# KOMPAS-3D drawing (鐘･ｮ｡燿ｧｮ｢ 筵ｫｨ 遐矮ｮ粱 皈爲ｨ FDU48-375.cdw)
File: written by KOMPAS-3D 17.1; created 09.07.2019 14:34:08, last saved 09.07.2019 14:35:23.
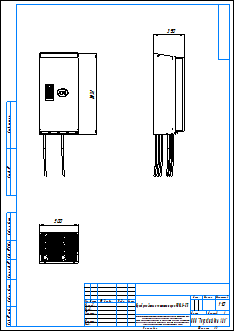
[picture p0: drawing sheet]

Sheet 1: A3, portrait

Title block, sheet 1: name: Преобразователи частоты серии FDU48-375; sheets: 1; sheet format: A3; stored path: \\adlc.lan\data\АДЛ_ПКД\3D-модели\Поставщики\Оборудование Emotron\Преобразователи частоты\Серия FDU 2.0\KOMPAS 2D\Преобразователи частоты серии FDU48-375.cdw

Views: Вид 1
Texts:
  user
  CONTINUOUS_RGB_0_0_0_THICK_0.18
  POLYLINE_STYLE_0.18_RGB_0_0_0
  Рама для чертежей
  Лит-Масса-Масштаб
  Материал-Предприятие
  Масштаб
  Изм.
  Лист
  № докум.
  Подп.
  Дата
  Лит.
  Разраб.
  Пров.
  Т.контр.
  Листов
  Внимание! Данный продукт является объектом авторского права ООО «Торговый Дом АДЛ».
  Запрещается изменение, копирование, распространение
  (в том числе путем копирования на другие сайты и ресурсы в Интернете)
  или любое иное использование информации и объектов без предварительного
  согласия правообладателя (ООО «Торговый Дом АДЛ»).
  Н.контр.
  Утв.
  ООО "Торговый дом АДЛ"
  Изменение
  Номер документа
  Подпись
  Обозначение документа
  Наименование изделия
  Масса изделия по ГОСТ 2.109-73
  Порядковый номер листа
  Общее количество листов в документе
  Характер работы, выполненной лицом, подписавшим документ
  Наименование или индекс предприятия, выпускающего документ
  Инв. № подл.
  Подп. и дата
  Взам. инв. №
  Инв. № дубл.
  Инвентарный номер подлинника по ГОСТ 2.501-68
  Подпись принявшего подлинник в отдел технической документации
  Инвентарный номер подлинника, взамен которого выпущен данный подлинник
  Инвентарный номер дубликата по ГОСТ 2.502-68
  Подпись принявшего дубликат в отдел технической документации
  Справ. №
  Перв. примен.
  Обозначение документа, взамен или на основании которого выпущен данный документ
  Обозначение документа, в котором впервые записан данный документ
  Подпись лица, копировавшего чертеж
  Обозначение формата листа
  !Рама для чертежа
Dimensions and other numbers on the sheet: 390; 1032; 500; 1:10; 1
